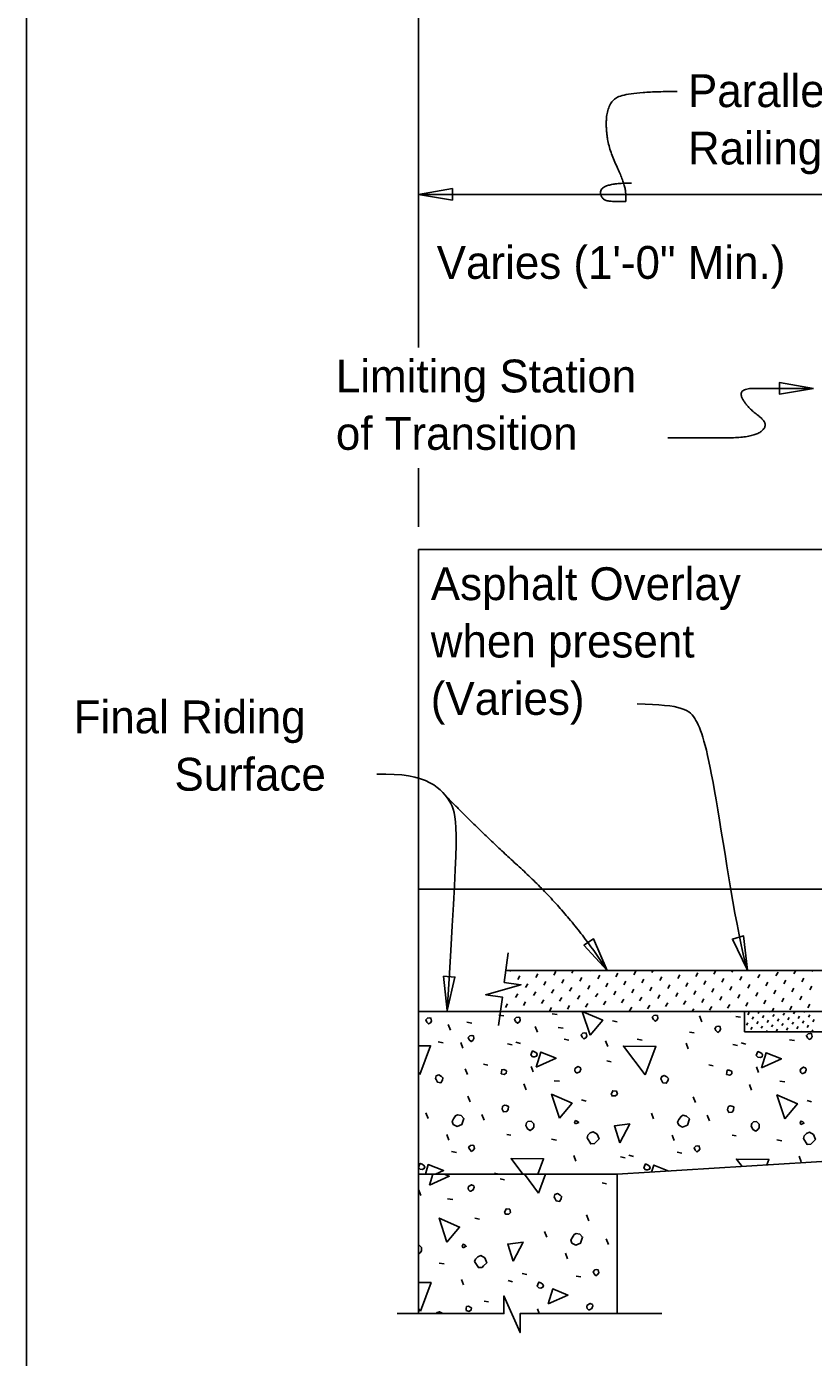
# Model space of a CAD drawing. Extents: x 1.5 to 68.7, y 0 to 31.1.
# Drawn here: x 1.47 to 6.3, y 8.86 to 17.03 of the extents above; entities that cross this region are included whole.
import ezdxf

# ---------------------------------------------------------------- set-up
doc = ezdxf.new("R2010")
doc.units = 0
for name, color, linetype in [('ActivePts-ConstElements', 7, 'Continuous'), ('Dimension', 7, 'Continuous'), ('Miscellaneous', 7, 'Continuous'), ('TextStructures', 7, 'Continuous'), ('TrafBarrierConc', 7, 'Continuous')]:
    doc.layers.add(name, color=color, linetype=linetype)

msp = doc.modelspace()

# ---------------------------------------------------------------- linework, layer by layer
at = {"layer": 'ActivePts-ConstElements'}
msp.add_lwpolyline([(1.4667, 28.1828), (42.5333, 28.1828), (42.5333, 1.7828), (1.4667, 1.7828)], close=True, dxfattribs=at)
at = {"layer": 'Dimension'}
for p, q in [((3.8717, 19.993), (3.8717, 15.0583)), ((3.8716, 14.3176), (3.8716, 13.9572))]:
    msp.add_line(p, q, dxfattribs=at)
for points in [[(3.8718, 15.9978), (4.08, 15.9625), (4.08, 16.0331)], [(6.2955, 14.8073), (6.0872, 14.8426), (6.0872, 14.772)], [(5.8901, 11.237), (5.8668, 11.4469), (5.799, 11.4275)], [(5.0307, 11.2353), (4.9464, 11.429), (4.8873, 11.3904)], [(4.0475, 10.9895), (4.0958, 11.1951), (4.0253, 11.1995)]]:
    msp.add_lwpolyline(points, close=True, dxfattribs=at)
for points in [[(3.8717, 15.9978), (7.4052, 15.9978)], [(4.3634, 10.8985), (4.3866, 11.0723), (4.2841, 11.0859), (4.3925, 11.1169), (4.5009, 11.1478), (4.3985, 11.1615), (4.4228, 11.3438)], [(5.3648, 9.1297), (4.4956, 9.1297), (4.4956, 9.0135), (4.3963, 9.2385), (4.3963, 9.1297), (3.7411, 9.1297)]]:
    msp.add_lwpolyline(points, dxfattribs=at)
for points, degree in [([(5.4596, 16.6291), (5.1506, 16.6291), (5.0242, 16.5518), (5.0242, 16.3059), (5.1436, 16.053), (5.1436, 15.9547), (5.1436, 15.9547), (4.9891, 15.9547), (4.9891, 16.0671), (5.1787, 16.0671)], 2), ([(5.4027, 14.504), (5.6164, 14.504), (5.9294, 14.504), (6.0287, 14.5885), (5.8846, 14.6929), (5.83, 14.8073), (6.0436, 14.8073), (6.2954, 14.8073)], 2), ([(5.2131, 12.8721), (5.4937, 12.8638), (5.58, 12.8123), (5.6787, 12.479), (5.824, 11.4682), (5.89, 11.2369)], 3), ([(3.6152, 12.4392), (3.9268, 12.4512), (4.1169, 12.247), (4.1169, 12.0935), (4.0474, 10.9894)], 3), ([(4.0341, 12.3137), (4.2082, 12.1286), (4.8016, 11.5859), (5.0307, 11.2353)], 2)]:
    msp.add_open_spline(points, degree=degree, dxfattribs=at)
at = {"layer": 'Miscellaneous'}
for p, q in [((4.4318, 11.2289), (4.435, 11.2345)), ((4.4806, 11.1801), (4.4936, 11.2025)), ((4.5913, 11.193), (4.6042, 11.2154)), ((4.7019, 11.206), (4.7149, 11.2284)), ((4.8125, 11.219), (4.8215, 11.2345)), ((4.8614, 11.1701), (4.8743, 11.1925)), ((4.9232, 11.2319), (4.9246, 11.2345)), ((4.972, 11.1831), (4.985, 11.2055)), ((5.0826, 11.1961), (5.0956, 11.2184)), ((5.1933, 11.209), (5.2062, 11.2314)), ((5.3039, 11.222), (5.3111, 11.2345)), ((5.3527, 11.1731), (5.3657, 11.1955)), ((5.4634, 11.1861), (5.4763, 11.2085)), ((5.574, 11.1991), (5.587, 11.2215)), ((5.6846, 11.212), (5.6976, 11.2344)), ((5.7953, 11.225), (5.8008, 11.2345)), ((5.8441, 11.1762), (5.8571, 11.1986)), ((5.9547, 11.1891), (5.9677, 11.2115)), ((6.0654, 11.2021), (6.0783, 11.2245)), ((6.176, 11.2151), (6.1872, 11.2345)), ((6.2248, 11.1662), (6.2378, 11.1886)), ((6.2866, 11.228), (6.2904, 11.2345)), ((4.5295, 11.1312), (4.5424, 11.1536)), ((4.6401, 11.1442), (4.6531, 11.1666)), ((4.6889, 11.0954), (4.7019, 11.1178)), ((4.7507, 11.1572), (4.7637, 11.1796)), ((4.7996, 11.1083), (4.8125, 11.1307)), ((4.9102, 11.1213), (4.9232, 11.1437)), ((5.0208, 11.1343), (5.0338, 11.1566)), ((5.0697, 11.0854), (5.0826, 11.1078)), ((5.1315, 11.1472), (5.1444, 11.1696)), ((5.1803, 11.0984), (5.1933, 11.1208)), ((5.2421, 11.1602), (5.2551, 11.1826)), ((5.2909, 11.1113), (5.3039, 11.1337)), ((5.4016, 11.1243), (5.4145, 11.1467)), ((5.5122, 11.1373), (5.5252, 11.1597)), ((5.561, 11.0884), (5.574, 11.1108)), ((5.6228, 11.1502), (5.6358, 11.1726)), ((5.6717, 11.1014), (5.6846, 11.1238)), ((5.7335, 11.1632), (5.7464, 11.1856)), ((5.7823, 11.1144), (5.7953, 11.1368)), ((5.8929, 11.1273), (5.9059, 11.1497)), ((6.0036, 11.1403), (6.0165, 11.1627)), ((6.0524, 11.0915), (6.0654, 11.1139)), ((6.1142, 11.1533), (6.1272, 11.1756)), ((6.163, 11.1044), (6.176, 11.1268)), ((6.2737, 11.1174), (6.2866, 11.1398)), ((4.4059, 11.0076), (4.4188, 11.03)), ((4.4677, 11.0694), (4.4806, 11.0918)), ((4.5165, 11.0206), (4.5295, 11.043)), ((4.5783, 11.0824), (4.5913, 11.1048)), ((4.6271, 11.0336), (4.6401, 11.056)), ((4.7378, 11.0465), (4.7507, 11.0689)), ((4.8484, 11.0595), (4.8614, 11.0819)), ((4.8972, 11.0107), (4.9102, 11.0331)), ((4.959, 11.0725), (4.972, 11.0948)), ((5.0079, 11.0236), (5.0208, 11.046)), ((5.1185, 11.0366), (5.1315, 11.059)), ((5.2291, 11.0495), (5.2421, 11.0719)), ((5.3398, 11.0625), (5.3527, 11.0849)), ((5.3886, 11.0137), (5.4016, 11.0361)), ((5.4504, 11.0755), (5.4634, 11.0979)), ((5.4992, 11.0266), (5.5122, 11.049)), ((5.6099, 11.0396), (5.6228, 11.062)), ((5.7205, 11.0526), (5.7335, 11.075)), ((5.7693, 11.0037), (5.7823, 11.0261)), ((5.8311, 11.0655), (5.8441, 11.0879)), ((5.88, 11.0167), (5.8929, 11.0391)), ((5.9418, 11.0785), (5.9547, 11.1009)), ((5.9906, 11.0297), (6.0036, 11.0521)), ((6.1012, 11.0426), (6.1142, 11.065)), ((6.2119, 11.0556), (6.2248, 11.078)), ((6.2607, 11.0068), (6.2737, 11.0291)), ((4.3648, 10.9618), (4.3948, 10.9565)), ((4.676, 10.9847), (4.6889, 11.0071)), ((4.6932, 10.9698), (4.7233, 10.9645)), ((4.7866, 10.9977), (4.7996, 11.0201)), ((5.1673, 10.9878), (5.1803, 11.0101)), ((5.278, 11.0007), (5.2909, 11.0231)), ((5.5503, 10.9816), (5.561, 11.0002)), ((5.6106, 10.9206), (5.5965, 10.9559)), ((5.6587, 10.9908), (5.6717, 11.0132)), ((5.7804, 10.9798), (5.7831, 10.9845)), ((5.8186, 10.9538), (5.8486, 10.9485)), ((5.8922, 10.9636), (5.9003, 10.9776)), ((5.9199, 10.9359), (5.928, 10.9499)), ((5.9557, 10.9717), (5.963, 10.9845)), ((5.9834, 10.944), (5.9915, 10.958)), ((6.0191, 10.9798), (6.0218, 10.9845)), ((6.0399, 10.9816), (6.0524, 11.0032)), ((6.0468, 10.9521), (6.0549, 10.9661)), ((6.1103, 10.9602), (6.1184, 10.9742)), ((6.138, 10.9325), (6.1461, 10.9465)), ((6.1501, 10.9938), (6.163, 11.0162)), ((6.1738, 10.9683), (6.1819, 10.9823)), ((6.2015, 10.9406), (6.2096, 10.9546)), ((6.2373, 10.9764), (6.242, 10.9845)), ((6.265, 10.9487), (6.2731, 10.9627)), ((6.2802, 10.9811), (6.2821, 10.9845)), ((4.0687, 10.8685), (4.0546, 10.9038)), ((4.1686, 10.9177), (4.1986, 10.9124)), ((4.6014, 10.8564), (4.5872, 10.8918)), ((4.7292, 10.8857), (4.7593, 10.8804)), ((5.0617, 10.9258), (5.0917, 10.9205)), ((5.8841, 10.9001), (5.8922, 10.9141)), ((5.9118, 10.8724), (5.9199, 10.8864)), ((5.9476, 10.9082), (5.9557, 10.9222)), ((5.9752, 10.8805), (5.9834, 10.8945)), ((6.0068, 10.8595), (6.011, 10.8668)), ((6.011, 10.9163), (6.0191, 10.9303)), ((6.0387, 10.8886), (6.0468, 10.9026)), ((6.0664, 10.8609), (6.0745, 10.8749)), ((6.0745, 10.9244), (6.0826, 10.9384)), ((6.1022, 10.8967), (6.1103, 10.9107)), ((6.1299, 10.869), (6.138, 10.883)), ((6.1657, 10.9048), (6.1738, 10.9188)), ((6.1934, 10.8771), (6.2015, 10.8911)), ((6.2269, 10.8595), (6.2292, 10.8634)), ((6.2292, 10.9129), (6.2373, 10.9269)), ((6.2569, 10.8852), (6.265, 10.8992)), ((6.2857, 10.8595), (6.2927, 10.8715)), ((6.2927, 10.921), (6.3008, 10.935)), ((3.9923, 10.7975), (4.0224, 10.7922)), ((4.1439, 10.7587), (4.1315, 10.7923)), ((4.4179, 10.7852), (4.4462, 10.7782)), ((4.4696, 10.7945), (4.4979, 10.7875)), ((4.7653, 10.8135), (4.7953, 10.8082)), ((5.0339, 10.7683), (5.0197, 10.8036)), ((5.2138, 10.8135), (5.2439, 10.8082)), ((5.5272, 10.7552), (5.5148, 10.7888)), ((5.5342, 10.8576), (5.5643, 10.8523)), ((5.8012, 10.7817), (5.8295, 10.7746)), ((5.8529, 10.791), (5.8812, 10.7839)), ((6.1486, 10.81), (6.1786, 10.8047)), ((4.1728, 10.5959), (4.1587, 10.6313)), ((4.2712, 10.6597), (4.2977, 10.6544)), ((4.5757, 10.6133), (4.5633, 10.6469)), ((5.0287, 10.6809), (5.0552, 10.6756)), ((5.6545, 10.6562), (5.681, 10.6509)), ((5.959, 10.6098), (5.9466, 10.6434)), ((4.5333, 10.5037), (4.5191, 10.5391)), ((4.7052, 10.559), (4.737, 10.5554)), ((5.9165, 10.5002), (5.9024, 10.5355)), ((6.0885, 10.5554), (6.1203, 10.5519)), ((4.1881, 10.4282), (4.174, 10.4635)), ((5.5714, 10.4246), (5.5572, 10.46)), ((4.8731, 10.4405), (4.9014, 10.4335)), ((6.2564, 10.437), (6.2847, 10.4299)), ((3.9318, 10.3274), (3.9176, 10.3627)), ((4.2752, 10.3163), (4.261, 10.3517)), ((5.3151, 10.3239), (5.3009, 10.3592)), ((5.6585, 10.3128), (5.6443, 10.3482)), ((4.0573, 10.1948), (4.0449, 10.2284)), ((4.4131, 10.228), (4.4378, 10.2244)), ((5.4406, 10.1913), (5.4282, 10.2249)), ((5.7963, 10.2244), (5.8211, 10.2209)), ((4.6888, 10.1997), (4.7189, 10.1944)), ((6.0721, 10.1961), (6.1022, 10.1908)), ((4.0754, 10.1237), (4.1055, 10.1184)), ((4.8373, 10.0653), (4.825, 10.0989)), ((5.1113, 10.0918), (5.1396, 10.0848)), ((5.163, 10.1011), (5.1913, 10.094)), ((5.4587, 10.1201), (5.4887, 10.1148)), ((6.2206, 10.0618), (6.2082, 10.0954)), ((4.3388, 9.9911), (4.3653, 9.9858)), ((4.3388, 9.9911), (4.3653, 9.9858)), ((3.8858, 9.8536), (3.8734, 9.8872)), ((4.3737, 9.9562), (4.4002, 9.9509)), ((4.9995, 9.9314), (5.026, 9.9261)), ((4.0502, 9.8342), (4.082, 9.8307)), ((4.9164, 9.6998), (4.9023, 9.7352)), ((4.2181, 9.7157), (4.2464, 9.7087)), ((4.6601, 9.5991), (4.6459, 9.6344)), ((5.0384, 9.5531), (5.0242, 9.5885)), ((4.7856, 9.4665), (4.7732, 9.5001)), ((3.9989, 9.44), (4.029, 9.4347)), ((4.1474, 9.3056), (4.135, 9.3392)), ((4.4214, 9.3321), (4.4497, 9.3251)), ((4.508, 9.3763), (4.5363, 9.3693)), ((4.8386, 9.3604), (4.8687, 9.3551)), ((4.2747, 9.2066), (4.3012, 9.2013)), ((4.6125, 9.1297), (4.6017, 9.1589))]:
    msp.add_line(p, q, dxfattribs=at)
for points in [[(3.9235, 10.9181), (3.9341, 10.9075), (3.9447, 10.9146), (3.9518, 10.9252), (3.9482, 10.9428), (3.9394, 10.9446), (3.927, 10.9428), (3.9164, 10.9322), (3.9235, 10.9181)], [(4.4682, 10.9221), (4.4788, 10.9115), (4.4894, 10.9186), (4.4964, 10.9292), (4.4929, 10.9468), (4.4841, 10.9486), (4.4717, 10.9468), (4.4611, 10.9362), (4.4682, 10.9221)], [(4.9248, 10.8378), (4.8771, 10.9845), (5.0026, 10.9297), (4.9248, 10.8378)], [(5.3132, 10.9341), (5.3238, 10.9235), (5.3344, 10.9306), (5.3415, 10.9412), (5.3379, 10.9589), (5.3291, 10.9606), (5.3167, 10.9589), (5.3061, 10.9483), (5.3132, 10.9341)], [(5.6977, 10.866), (5.7083, 10.8554), (5.7189, 10.8624), (5.726, 10.8731), (5.7224, 10.8907), (5.7136, 10.8925), (5.7012, 10.8907), (5.6906, 10.8801), (5.6977, 10.866)], [(4.1838, 10.8099), (4.1944, 10.7993), (4.205, 10.8063), (4.2121, 10.8169), (4.2086, 10.8346), (4.1997, 10.8364), (4.1873, 10.8346), (4.1767, 10.824), (4.1838, 10.8099)], [(4.8767, 10.8259), (4.8873, 10.8153), (4.8979, 10.8224), (4.9049, 10.833), (4.9014, 10.8507), (4.8926, 10.8524), (4.8802, 10.8507), (4.8696, 10.84), (4.8767, 10.8259)], [(6.2599, 10.8224), (6.2705, 10.8118), (6.2811, 10.8188), (6.2882, 10.8294), (6.2847, 10.8471), (6.2758, 10.8489), (6.2635, 10.8471), (6.2529, 10.8365), (6.2599, 10.8224)], [(3.8717, 10.7735), (3.9459, 10.7729), (3.8805, 10.5979)], [(4.5722, 10.7061), (4.5845, 10.7044), (4.5969, 10.7097), (4.6004, 10.7203), (4.5951, 10.7291), (4.5845, 10.7362), (4.5722, 10.7415), (4.5651, 10.7273), (4.5616, 10.7167), (4.5722, 10.7061)], [(4.5938, 10.6421), (4.6221, 10.734), (4.7158, 10.6969), (4.5938, 10.6421)], [(5.2638, 10.5943), (5.1294, 10.7711), (5.3292, 10.7693), (5.2638, 10.5943)], [(5.9554, 10.7026), (5.9678, 10.7008), (5.9802, 10.7061), (5.9837, 10.7167), (5.9784, 10.7256), (5.9678, 10.7327), (5.9554, 10.738), (5.9484, 10.7238), (5.9448, 10.7132), (5.9554, 10.7026)], [(5.9771, 10.6385), (6.0054, 10.7304), (6.0991, 10.6933), (5.9771, 10.6385)], [(4.379, 10.6014), (4.3985, 10.5961), (4.4109, 10.6049), (4.4126, 10.6173), (4.4091, 10.6208), (4.3949, 10.6279), (4.3826, 10.6261), (4.3808, 10.6138), (4.379, 10.6014)], [(4.8413, 10.6067), (4.8484, 10.6067), (4.8625, 10.6138), (4.8678, 10.6297), (4.8661, 10.6385), (4.8519, 10.6456), (4.8342, 10.635), (4.8307, 10.6244), (4.8342, 10.6138), (4.8413, 10.6067)], [(5.7623, 10.5979), (5.7818, 10.5926), (5.7941, 10.6014), (5.7959, 10.6138), (5.7924, 10.6173), (5.7782, 10.6244), (5.7658, 10.6226), (5.7641, 10.6102), (5.7623, 10.5979)], [(6.2246, 10.6032), (6.2317, 10.6032), (6.2458, 10.6102), (6.2511, 10.6261), (6.2493, 10.635), (6.2352, 10.6421), (6.2175, 10.6314), (6.214, 10.6208), (6.2175, 10.6102), (6.2246, 10.6032)], [(3.8805, 10.5979), (3.8717, 10.6095)], [(3.9795, 10.566), (3.9884, 10.5501), (4.0096, 10.5466), (4.0184, 10.5625), (4.0219, 10.5766), (4.0131, 10.5855), (3.9972, 10.5943), (3.9813, 10.589), (3.976, 10.5731), (3.9795, 10.566)], [(5.3628, 10.5625), (5.3716, 10.5466), (5.3928, 10.5431), (5.4017, 10.559), (5.4052, 10.5731), (5.3964, 10.582), (5.3805, 10.5908), (5.3646, 10.5855), (5.3593, 10.5696), (5.3628, 10.5625)], [(4.7366, 10.3287), (4.6888, 10.4754), (4.8143, 10.4206), (4.7366, 10.3287)], [(5.0605, 10.4653), (5.0817, 10.4653), (5.0923, 10.4759), (5.087, 10.4953), (5.064, 10.4971), (5.0605, 10.4865), (5.0552, 10.4777), (5.0605, 10.4653), (5.057, 10.4688)], [(6.1198, 10.3252), (6.0721, 10.4719), (6.1976, 10.4171), (6.1198, 10.3252)], [(4.3848, 10.3835), (4.3936, 10.3676), (4.4131, 10.3694), (4.4219, 10.3818), (4.4237, 10.4012), (4.4113, 10.4065), (4.4025, 10.4083), (4.3918, 10.4047), (4.3883, 10.4012), (4.3848, 10.3835)], [(5.7681, 10.38), (5.7769, 10.3641), (5.7963, 10.3658), (5.8052, 10.3782), (5.8069, 10.3977), (5.7946, 10.403), (5.7857, 10.4047), (5.7751, 10.4012), (5.7716, 10.3977), (5.7681, 10.38)], [(4.0856, 10.2903), (4.1086, 10.2779), (4.1386, 10.2903), (4.151, 10.3274), (4.1333, 10.3451), (4.1103, 10.3504), (4.0997, 10.3433), (4.0874, 10.3239), (4.0785, 10.3079), (4.0856, 10.2903)], [(4.5297, 10.2845), (4.5403, 10.2633), (4.558, 10.2527), (4.5722, 10.2633), (4.5792, 10.2739), (4.5792, 10.2951), (4.5633, 10.311), (4.5439, 10.3093), (4.535, 10.3004), (4.5297, 10.2845)], [(4.8356, 10.2934), (4.855, 10.3022), (4.8479, 10.3093), (4.8356, 10.3146), (4.8303, 10.3022), (4.8356, 10.2934)], [(5.1082, 10.1771), (5.0746, 10.2814), (5.1683, 10.2938), (5.1082, 10.1771)], [(5.4689, 10.2867), (5.4918, 10.2744), (5.5219, 10.2867), (5.5343, 10.3239), (5.5166, 10.3415), (5.4936, 10.3468), (5.483, 10.3398), (5.4706, 10.3203), (5.4618, 10.3044), (5.4689, 10.2867)], [(5.913, 10.281), (5.9236, 10.2598), (5.9413, 10.2492), (5.9554, 10.2598), (5.9625, 10.2704), (5.9625, 10.2916), (5.9466, 10.3075), (5.9272, 10.3057), (5.9183, 10.2969), (5.913, 10.281)], [(6.2188, 10.2898), (6.2383, 10.2987), (6.2312, 10.3057), (6.2188, 10.311), (6.2135, 10.2987), (6.2188, 10.2898)], [(4.9063, 10.2085), (4.9292, 10.1714), (4.9522, 10.1732), (4.9611, 10.182), (4.9805, 10.2014), (4.9681, 10.2315), (4.9434, 10.2456), (4.9257, 10.2386), (4.9116, 10.2244), (4.9063, 10.2085)], [(6.2339, 10.205), (6.2568, 10.1679), (6.2798, 10.1696), (6.2887, 10.1785), (6.3081, 10.1979), (6.2957, 10.228), (6.271, 10.2421), (6.2533, 10.235), (6.2392, 10.2209), (6.2339, 10.205)], [(4.1868, 10.136), (4.1974, 10.1254), (4.208, 10.1325), (4.2151, 10.1431), (4.2115, 10.1608), (4.2027, 10.1625), (4.1903, 10.1608), (4.1797, 10.1502), (4.1868, 10.136)], [(5.5701, 10.1325), (5.5807, 10.1219), (5.5913, 10.129), (5.5983, 10.1396), (5.5948, 10.1572), (5.586, 10.159), (5.5736, 10.1572), (5.563, 10.1466), (5.5701, 10.1325)], [(3.8823, 10.0163), (3.8947, 10.0145), (3.907, 10.0198), (3.9106, 10.0304), (3.9053, 10.0392), (3.8947, 10.0463), (3.8823, 10.0516), (3.8752, 10.0375), (3.8717, 10.0269)], [(4.5131, 9.9844), (4.4396, 10.0812), (4.6393, 10.0795), (4.6038, 9.9844)], [(5.2656, 10.0127), (5.2779, 10.011), (5.2903, 10.0163), (5.2939, 10.0269), (5.2885, 10.0357), (5.2779, 10.0428), (5.2656, 10.0481), (5.2585, 10.0339), (5.255, 10.0233), (5.2656, 10.0127)], [(5.8574, 10.0323), (5.8229, 10.0777), (6.0226, 10.0759), (6.0099, 10.0418)], [(3.8717, 10.0269), (3.8823, 10.0163)], [(3.9139, 9.9844), (3.9322, 10.0441), (4.0259, 10.007), (3.9758, 9.9844)], [(3.9388, 9.9173), (3.9595, 9.9844)], [(4.0296, 9.9844), (4.0608, 9.9721), (3.9388, 9.9173)], [(4.6088, 9.8695), (4.5215, 9.9844)], [(4.6517, 9.9844), (4.6088, 9.8695)], [(5.3023, 9.9976), (5.3155, 10.0406), (5.4074, 10.0042)], [(4.1863, 9.8819), (4.1934, 9.8819), (4.2075, 9.889), (4.2128, 9.9049), (4.2111, 9.9137), (4.1969, 9.9208), (4.1792, 9.9102), (4.1757, 9.8996), (4.1792, 9.889), (4.1863, 9.8819)], [(4.7078, 9.8377), (4.7166, 9.8218), (4.7379, 9.8183), (4.7467, 9.8342), (4.7502, 9.8483), (4.7414, 9.8572), (4.7255, 9.866), (4.7096, 9.8607), (4.7043, 9.8448), (4.7078, 9.8377)], [(4.4055, 9.7405), (4.4267, 9.7405), (4.4373, 9.7511), (4.432, 9.7705), (4.409, 9.7723), (4.4055, 9.7617), (4.4002, 9.7529), (4.4055, 9.7405), (4.402, 9.744)], [(4.0467, 9.569), (3.9989, 9.7157), (4.1244, 9.6609), (4.0467, 9.569)], [(4.1456, 9.5337), (4.1651, 9.5425), (4.158, 9.5496), (4.1456, 9.5549), (4.1403, 9.5425), (4.1456, 9.5337)], [(4.4532, 9.4524), (4.4197, 9.5566), (4.5133, 9.569), (4.4532, 9.4524)], [(4.8139, 9.562), (4.8368, 9.5496), (4.8669, 9.562), (4.8793, 9.5991), (4.8616, 9.6168), (4.8386, 9.6221), (4.828, 9.615), (4.8156, 9.5955), (4.8068, 9.5796), (4.8139, 9.562)], [(3.8717, 9.4957), (3.8823, 9.5036), (3.8893, 9.5142), (3.8893, 9.5354), (3.8734, 9.5513), (3.8717, 9.5512)], [(4.2164, 9.4488), (4.2393, 9.4117), (4.2623, 9.4135), (4.2712, 9.4223), (4.2906, 9.4417), (4.2782, 9.4718), (4.2535, 9.4859), (4.2358, 9.4789), (4.2217, 9.4647), (4.2164, 9.4488)], [(4.95, 9.3728), (4.9606, 9.3622), (4.9712, 9.3693), (4.9783, 9.3799), (4.9747, 9.3975), (4.9659, 9.3993), (4.9535, 9.3975), (4.9429, 9.3869), (4.95, 9.3728)], [(3.8717, 9.3205), (3.9494, 9.3198), (3.884, 9.1448)], [(4.6106, 9.2879), (4.6229, 9.2862), (4.6353, 9.2915), (4.6389, 9.3021), (4.6336, 9.3109), (4.6229, 9.318), (4.6106, 9.3233), (4.6035, 9.3092), (4.6, 9.2986), (4.6106, 9.2879)], [(4.6671, 9.189), (4.6954, 9.2809), (4.7891, 9.2438), (4.6671, 9.189)], [(3.884, 9.1448), (3.8717, 9.161)], [(4.1635, 9.1483), (4.1829, 9.143), (4.1953, 9.1518), (4.1971, 9.1642), (4.1935, 9.1677), (4.1794, 9.1748), (4.167, 9.173), (4.1653, 9.1607), (4.1635, 9.1483)], [(4.9146, 9.1536), (4.9217, 9.1536), (4.9358, 9.1607), (4.9411, 9.1766), (4.9394, 9.1854), (4.9252, 9.1925), (4.9076, 9.1819), (4.904, 9.1713), (4.9076, 9.1607), (4.9146, 9.1536)], [(4.0193, 9.1297), (4.0166, 9.1324), (4.0007, 9.1412), (3.9848, 9.1359), (3.9827, 9.1297)]]:
    msp.add_lwpolyline(points, dxfattribs=at)
at = {"layer": 'TrafBarrierConc'}
for p, q in [((3.8717, 13.8178), (3.8717, 11.7345)), ((14.1461, 13.8178), (3.8717, 13.8178)), ((3.8717, 11.7345), (14.1461, 11.7345)), ((3.8718, 11.7345), (3.8718, 9.1297)), ((4.4082, 11.2345), (6.67, 11.2345)), ((3.8717, 10.9845), (18.1441, 10.9845)), ((5.8718, 10.9845), (5.8718, 10.8595)), ((5.8718, 10.8595), (11.8162, 10.8595)), ((5.0917, 9.9844), (9.0917, 10.2344)), ((5.0917, 9.9845), (3.8717, 9.9845)), ((5.0918, 9.9845), (5.0918, 9.1297)), ((5.0918, 9.9844), (5.0918, 9.1297))]:
    msp.add_line(p, q, dxfattribs=at)

# ---------------------------------------------------------------- texts
at = {"layer": 'Dimension'}
for s, p in [('Parallel Portion of Vertical Face Retrofit ', (5.5257, 16.5332)), ('Railing if present (See Note 1)', (5.5257, 16.1812)), ('Limiting Station', (3.3647, 14.7822)), ('of Transition', (3.3647, 14.4302)), ('Asphalt Overlay', (3.9472, 13.5078)), ('when present', (3.9472, 13.1558)), ('(Varies)', (3.9472, 12.8038)), ('Final Riding ', (1.7555, 12.6904)), ('Surface', (2.3743, 12.3384))]:
    msp.add_text(s, height=0.2016, dxfattribs=at).set_placement(p)
at = {"layer": 'TextStructures'}
msp.add_text('Varies (1\'-0" Min.)', height=0.2016, dxfattribs=at).set_placement((3.9837, 15.4794))

doc.saveas('drawing.dxf')
